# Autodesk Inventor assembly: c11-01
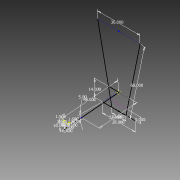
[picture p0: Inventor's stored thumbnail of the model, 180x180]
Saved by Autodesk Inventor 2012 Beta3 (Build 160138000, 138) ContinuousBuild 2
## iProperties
Created: 2011-01
Part Number: c11-01
Document SubType Name: Assembly
Designer: Beta-8540w
Author: Beta-8540w
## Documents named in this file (2)
- C:\Inventor 2012 Essentials\Assemblies\Chapter 11\c11-01.iam
- C:\Inventor 2012 Essentials\Parts\Chapter 11\c11-01.ipt
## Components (1 placed, 1 different names)
1. c11-01:1
